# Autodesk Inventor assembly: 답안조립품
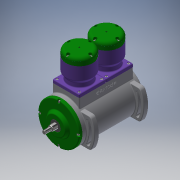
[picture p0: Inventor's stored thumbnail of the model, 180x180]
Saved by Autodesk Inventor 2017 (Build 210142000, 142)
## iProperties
Part Number: 답안조립품
Material: 일반
Document SubType Name: Assembly
Designer: Administrator
Mass: 7371.37 g
Surface Area: 5215.2 cm^2
Volume: 2062.19 cm^3
Density: 3.57453 g/cm^3
Author: Administrator
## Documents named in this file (16)
- C:\Users\Administrator\Desktop\620106V1012\답안조립품.iam
- C:\Users\Administrator\Desktop\620106V1012\너트 M4.ipt
- C:\Users\Administrator\Desktop\620106V1012\베어링 6303.ipt
- C:\Users\Administrator\Desktop\620106V1012\본체.ipt
- C:\Users\Administrator\Desktop\620106V1012\볼트 M4 x 12.ipt
- C:\Users\Administrator\Desktop\620106V1012\볼트 M5 x 20.ipt
- C:\Users\Administrator\Desktop\620106V1012\실린더.ipt
- C:\Users\Administrator\Desktop\620106V1012\실린더헤드.ipt
- C:\Users\Administrator\Desktop\620106V1012\앞커버.ipt
- C:\Users\Administrator\Desktop\620106V1012\오일 실 17 x 32 x 8.ipt
- C:\Users\Administrator\Desktop\620106V1012\육각 머리 볼트 M4 x 16.ipt
- C:\Users\Administrator\Desktop\620106V1012\커넥팅로드 엔드.ipt
- C:\Users\Administrator\Desktop\620106V1012\커넥팅로드.ipt
- C:\Users\Administrator\Desktop\620106V1012\크랭크축.ipt
- C:\Users\Administrator\Desktop\620106V1012\피스톤.ipt
- C:\Users\Administrator\Desktop\620106V1012\피스톤핀.ipt
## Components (4 placed, 2 different names)
1. 피스톤:1
2. 피스톤핀:1
3. 피스톤핀:2
4. 피스톤:2
